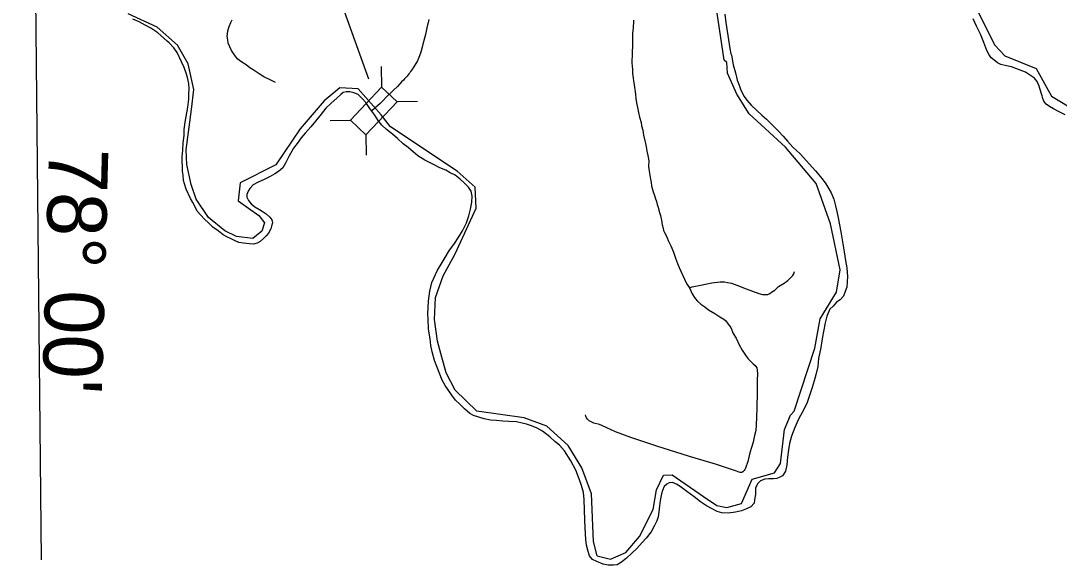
# Model space of a CAD drawing. Extents: x 2290615 to 2522933, y 819489 to 1012715.
# Drawn here: x 2295217 to 2306578, y 884249 to 890202 of the extents above; entities that cross this region are included whole.
import ezdxf

# ---------------------------------------------------------------- set-up
doc = ezdxf.new("R2010")
doc.units = 0
for name, color, linetype in [('Exist Boundary Political CountyLine', 7, 'Continuous'), ('Exist Hydrographic Misc Water Feature', 7, 'Continuous'), ('Exist Road Non-System Type 51', 7, 'Continuous'), ('Exist Road Secondary Structure Standard Bridge CELL', 7, 'Continuous'), ('Exist Road Secondary Structure Standard Bridge Number Label', 7, 'Continuous'), ('Exist Road Secondary Type 20 Attributed', 7, 'Continuous'), ('Map Preparation Longitude Latitude Label', 7, 'Continuous'), ('Map Preparation Longitude Latitude Lines', 7, 'Continuous')]:
    doc.layers.add(name, color=color, linetype=linetype)

msp = doc.modelspace()

# ---------------------------------------------------------------- linework, layer by layer
at = {"layer": 'Exist Boundary Political CountyLine'}
for points in [[(2297953, 887927), (2297928, 887881), (2297900, 887850), (2297873, 887820), (2297835, 887790), (2297803, 887769), (2297763, 887761), (2297721, 887764), (2297655, 887770), (2297601, 887777), (2297563, 887795), (2297517, 887818), (2297477, 887836), (2297432, 887863), (2297376, 887907), (2297319, 887946), (2297267, 887997), (2297231, 888029), (2297182, 888081), (2297148, 888122), (2297123, 888166), (2297099, 888214), (2297072, 888259), (2297027, 888361), (2297008, 888421), (2296998, 888456), (2296993, 888514), (2296987, 888558), (2296983, 888714), (2296988, 888786), (2296994, 888868), (2297003, 888948), (2297006, 889014), (2297015, 889094), (2297045, 889257), (2297054, 889347), (2297056, 889403), (2297059, 889457), (2297055, 889515), (2297042, 889582), (2297027, 889630), (2297005, 889692), (2296976, 889752), (2296927, 889855), (2296890, 889907), (2296840, 889960), (2296820, 889980), (2296717, 890069), (2296638, 890122), (2296576, 890155), (2296512, 890191), (2296441, 890220)], [(2302920, 890275), (2302929, 890185), (2302974, 889900), (2302985, 889842), (2302991, 889828), (2303012, 889721), (2303035, 889635), (2303056, 889553), (2303076, 889499), (2303093, 889445), (2303132, 889374), (2303162, 889334), (2303207, 889281), (2303324, 889170), (2303374, 889127), (2303504, 889000), (2303558, 888941), (2303607, 888885), (2303665, 888822), (2303744, 888749), (2303912, 888561), (2303983, 888475), (2304026, 888420), (2304056, 888364), (2304083, 888321), (2304111, 888251), (2304128, 888195), (2304145, 888115), (2304158, 888047), (2304189, 887896), (2304224, 887674), (2304239, 887581), (2304255, 887499), (2304262, 887407), (2304259, 887349), (2304254, 887291), (2304238, 887243), (2304217, 887192)], [(2305834, 889797), (2305810, 889829), (2305787, 889876), (2305754, 889964), (2305717, 890057), (2305672, 890145), (2305636, 890225)], [(2306644, 889174), (2306578, 889205), (2306514, 889240), (2306472, 889264), (2306435, 889290), (2306411, 889325), (2306399, 889351), (2306390, 889381), (2306378, 889425), (2306357, 889489), (2306337, 889538), (2306306, 889576), (2306264, 889605), (2306208, 889639), (2306105, 889680), (2306055, 889697), (2306001, 889711), (2305939, 889726), (2305903, 889744), (2305862, 889777), (2305834, 889797)], [(2300555, 885821), (2300491, 885825), (2300423, 885830), (2300355, 885835), (2300287, 885851), (2300227, 885866), (2300169, 885887), (2300128, 885909), (2300072, 885958), (2300019, 886010), (2299973, 886055), (2299932, 886109), (2299859, 886214), (2299826, 886274), (2299769, 886421), (2299742, 886487), (2299719, 886582), (2299702, 886652), (2299694, 886724), (2299679, 886830), (2299673, 886938), (2299671, 886996), (2299674, 887068), (2299677, 887136), (2299692, 887244), (2299715, 887340), (2299775, 887475), (2299815, 887539), (2299860, 887614), (2299909, 887694), (2299956, 887756), (2300010, 887841), (2300051, 887905), (2300092, 887992), (2300119, 888070), (2300136, 888144), (2300151, 888220), (2300155, 888286), (2300144, 888340), (2300114, 888384), (2300069, 888431), (2300025, 888469), (2299968, 888514), (2299916, 888540), (2299866, 888567), (2299803, 888594), (2299733, 888630), (2299639, 888679), (2299562, 888726), (2299508, 888769), (2299455, 888815), (2299401, 888858), (2299338, 888915), (2299282, 888963), (2299219, 889014), (2299167, 889062), (2299128, 889111), (2299091, 889171), (2299035, 889242), (2298992, 889307), (2298952, 889353), (2298907, 889397), (2298859, 889414), (2298817, 889424), (2298775, 889427), (2298743, 889419), (2298717, 889396), (2298680, 889360), (2298610, 889299), (2298555, 889247), (2298502, 889180), (2298442, 889106), (2298389, 889043), (2298328, 888975), (2298285, 888922), (2298239, 888860), (2298202, 888811), (2298151, 888717), (2298113, 888644), (2298084, 888596), (2298036, 888556), (2297995, 888527), (2297945, 888501), (2297874, 888464), (2297814, 888439), (2297760, 888409), (2297723, 888370), (2297703, 888338), (2297689, 888302), (2297690, 888272), (2297708, 888236), (2297738, 888202), (2297779, 888169), (2297845, 888128), (2297902, 888092), (2297942, 888053), (2297962, 888025), (2297969, 887991), (2297961, 887955), (2297953, 887927)], [(2304217, 887192), (2304181, 887152), (2304142, 887124), (2304106, 887083), (2304070, 887049), (2304035, 886973), (2304016, 886898), (2303999, 886804), (2303990, 886746), (2303969, 886630), (2303946, 886510), (2303937, 886422), (2303918, 886344), (2303897, 886265), (2303874, 886193), (2303820, 886029), (2303788, 885958), (2303725, 885844), (2303687, 885755), (2303649, 885659), (2303628, 885579), (2303617, 885509), (2303604, 885432), (2303597, 885348), (2303584, 885278), (2303550, 885226), (2303520, 885212), (2303489, 885197), (2303451, 885195), (2303399, 885194), (2303357, 885190), (2303309, 885171), (2303279, 885141), (2303256, 885095), (2303254, 885057), (2303254, 885021), (2303245, 884963), (2303240, 884927), (2303204, 884886), (2303158, 884866), (2303102, 884843), (2303037, 884829), (2302955, 884818), (2302887, 884821), (2302837, 884836), (2302780, 884866), (2302720, 884899), (2302652, 884942), (2302583, 884996), (2302504, 885053), (2302446, 885100), (2302398, 885132), (2302347, 885153), (2302311, 885149), (2302284, 885134), (2302256, 885108), (2302236, 885064), (2302227, 885030), (2302214, 884958), (2302206, 884898), (2302199, 884834), (2302190, 884777), (2302174, 884733), (2302147, 884677), (2302113, 884615), (2302058, 884546), (2302015, 884496), (2301957, 884433), (2301900, 884377), (2301843, 884324), (2301789, 884281), (2301743, 884253), (2301700, 884249), (2301643, 884250), (2301589, 884259), (2301519, 884291), (2301471, 884312), (2301438, 884350), (2301426, 884397), (2301405, 884469), (2301399, 884531), (2301391, 884659), (2301388, 884743), (2301380, 884969), (2301373, 885043), (2301350, 885122), (2301331, 885182), (2301290, 885288), (2301233, 885389), (2301166, 885498), (2301110, 885560), (2301061, 885603), (2301005, 885654), (2300926, 885716), (2300868, 885747), (2300805, 885774), (2300751, 885792), (2300701, 885803), (2300641, 885816), (2300555, 885821)]]:
    msp.add_lwpolyline(points, dxfattribs=at)
at = {"layer": 'Exist Hydrographic Misc Water Feature'}
for points in [[(2305596, 890490), (2305873, 889934), (2305983, 889820), (2306326, 889682), (2306492, 889378), (2307062, 889037)], [(2297028, 888791), (2297085, 889231), (2297109, 889451), (2297048, 889730), (2296932, 889937), (2296708, 890134), (2296392, 890277)], [(2303680, 885932), (2303906, 886624), (2303961, 886942), (2304141, 887234), (2304180, 887479), (2304075, 887983), (2303920, 888423), (2303583, 888820), (2303187, 889184), (2303052, 889399), (2302949, 889631), (2302940, 889745), (2302914, 889770), (2302834, 890286)], [(2301523, 884353), (2301484, 884508), (2301462, 885031), (2301356, 885315), (2301207, 885558), (2300972, 885771), (2300725, 885860), (2300206, 885935), (2299969, 886163), (2299872, 886351), (2299813, 886565), (2299777, 886698), (2299744, 886936), (2299755, 887177), (2299838, 887414), (2299970, 887653), (2300198, 888152), (2300188, 888384), (2299990, 888559), (2299262, 889043), (2299160, 889175), (2298908, 889460), (2298709, 889469), (2298537, 889327), (2298274, 889022), (2298006, 888628), (2297616, 888432), (2297596, 888235), (2297821, 888074), (2297882, 887991), (2297853, 887902), (2297755, 887821), (2297577, 887843), (2297450, 887904), (2297270, 888052), (2297137, 888253), (2297080, 888412), (2297032, 888630), (2297028, 888791)], [(2301523, 884353), (2301670, 884315), (2301838, 884387), (2301987, 884563), (2302134, 884858), (2302173, 885073), (2302250, 885233), (2302344, 885236), (2302687, 885001), (2302831, 884901), (2302943, 884880), (2303103, 884922), (2303217, 885190), (2303463, 885260), (2303528, 885361), (2303574, 885731), (2303639, 885888), (2303680, 885932)]]:
    msp.add_lwpolyline(points, dxfattribs=at)
at = {"layer": 'Exist Road Non-System Type 51'}
for points in [[(2298004, 889527), (2297945, 889558), (2297875, 889588), (2297825, 889622), (2297761, 889666), (2297723, 889689), (2297683, 889719), (2297624, 889757), (2297593, 889782), (2297569, 889807), (2297544, 889845), (2297521, 889879), (2297504, 889919), (2297487, 889959), (2297481, 889995), (2297474, 890033), (2297477, 890061), (2297481, 890094), (2297495, 890141), (2297514, 890183), (2297531, 890213)], [(2301921, 890209), (2301919, 890183), (2301918, 890141), (2301916, 890125), (2301914, 890095), (2301911, 890063), (2301911, 890007), (2301910, 889969), (2301910, 889947), (2301908, 889915), (2301907, 889875), (2301905, 889845), (2301905, 889817), (2301904, 889773), (2301904, 889739), (2301905, 889709), (2301909, 889665), (2301911, 889627), (2301918, 889579), (2301922, 889543), (2301927, 889507), (2301933, 889473), (2301937, 889429), (2301942, 889395), (2301946, 889353), (2301949, 889327), (2301957, 889286), (2301966, 889253), (2301976, 889199), (2301985, 889147), (2302003, 889090), (2302009, 889055), (2302022, 889008), (2302031, 888952), (2302044, 888890), (2302052, 888862), (2302061, 888806), (2302068, 888778), (2302076, 888730)], [(2302076, 888730), (2302090, 888670), (2302084, 888611), (2302089, 888581), (2302095, 888535), (2302106, 888469), (2302112, 888435), (2302119, 888397), (2302129, 888358), (2302137, 888332), (2302150, 888292), (2302158, 888266), (2302172, 888226), (2302181, 888192), (2302189, 888165), (2302199, 888133), (2302205, 888104), (2302215, 888073), (2302220, 888053), (2302226, 888023), (2302229, 887995), (2302235, 887971), (2302246, 887935), (2302250, 887909), (2302259, 887887), (2302273, 887860), (2302290, 887829), (2302300, 887799), (2302329, 887741), (2302358, 887673), (2302379, 887607), (2302402, 887547), (2302420, 887505), (2302456, 887425), (2302501, 887329), (2302532, 887283)], [(2302532, 887283), (2302564, 887292), (2302652, 887312), (2302778, 887336), (2302870, 887346), (2302916, 887348), (2302948, 887342), (2302994, 887332), (2303052, 887310), (2303154, 887272), (2303224, 887246), (2303292, 887220), (2303332, 887210), (2303354, 887208), (2303370, 887208), (2303390, 887210), (2303412, 887220), (2303432, 887234), (2303466, 887256), (2303508, 887296), (2303568, 887334), (2303610, 887364), (2303640, 887396), (2303664, 887418), (2303676, 887436), (2303682, 887462)], [(2302532, 887283), (2302562, 887218), (2302594, 887166), (2302622, 887138), (2302658, 887104), (2302700, 887074), (2302742, 887042), (2302810, 887000), (2302864, 886964), (2302908, 886940), (2302932, 886920), (2302956, 886886), (2302984, 886850), (2303012, 886784), (2303044, 886730), (2303078, 886660), (2303110, 886602), (2303138, 886558), (2303170, 886510), (2303208, 886474), (2303228, 886452), (2303252, 886434), (2303268, 886408), (2303274, 886382), (2303276, 886342), (2303274, 886274), (2303272, 886147), (2303270, 885963), (2303264, 885781), (2303258, 885723), (2303246, 885667), (2303228, 885593), (2303194, 885477), (2303172, 885381), (2303146, 885309), (2303139, 885296), (2303132, 885284), (2303116, 885270), (2303104, 885264), (2303087, 885264), (2303036, 885281), (2302816, 885353), (2302534, 885439), (2302176, 885551), (2301892, 885645), (2301723, 885707), (2301629, 885751), (2301573, 885777), (2301549, 885787), (2301487, 885803), (2301457, 885817), (2301437, 885827), (2301417, 885845), (2301407, 885859), (2301399, 885879), (2301397, 885893)]]:
    msp.add_lwpolyline(points, dxfattribs=at)
at = {"layer": 'Exist Road Secondary Structure Standard Bridge CELL'}
for p, q in [((2299159, 889701), (2299165, 889475)), ((2299559, 889321), (2299333, 889316)), ((2298826, 889113), (2298600, 889107)), ((2298991, 888957), (2298996, 888731))]:
    msp.add_line(p, q, dxfattribs=at)
msp.add_lwpolyline([(2299333, 889316), (2298991, 888956), (2298823, 889116), (2299165, 889475)], close=True, dxfattribs=at)
at = {"layer": 'Exist Road Secondary Structure Standard Bridge Number Label'}
msp.add_lwpolyline([(2299024, 889563), (2298292, 891606), (2298446, 894688)], dxfattribs=at)
at = {"layer": 'Exist Road Secondary Type 20 Attributed'}
msp.add_lwpolyline([(2299682, 890216), (2299660, 890127), (2299646, 890052), (2299623, 889971), (2299617, 889945), (2299608, 889915), (2299593, 889860), (2299578, 889818), (2299564, 889783), (2299560, 889774), (2299553, 889758), (2299539, 889736), (2299522, 889707), (2299504, 889676), (2299481, 889648), (2299473, 889634), (2299463, 889621), (2299453, 889609), (2299443, 889597), (2299429, 889582), (2299415, 889566), (2299403, 889552), (2299383, 889533), (2299365, 889512), (2299337, 889485), (2299296, 889443), (2299272, 889422), (2299216, 889367), (2299180, 889332), (2299148, 889299), (2299056, 889216)], dxfattribs=at)
at = {"layer": 'Map Preparation Longitude Latitude Lines'}
msp.add_line((2295443, 884307), (2295217, 906749), dxfattribs=at)

# ---------------------------------------------------------------- texts
at = {"layer": 'Map Preparation Longitude Latitude Label'}
msp.add_text("78° 00'", height=650, rotation=268.4385, dxfattribs=at).set_placement((2295526, 888819))

doc.saveas('drawing.dxf')
